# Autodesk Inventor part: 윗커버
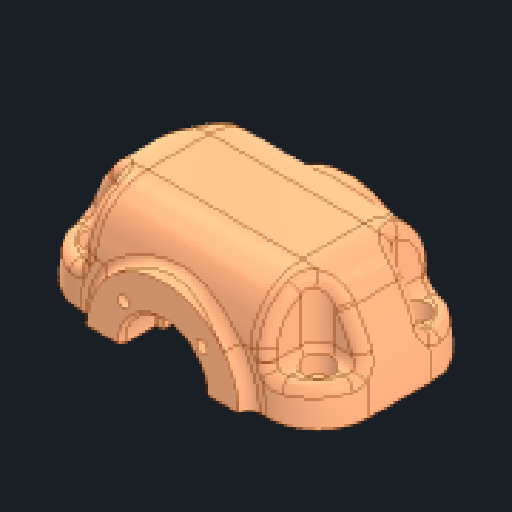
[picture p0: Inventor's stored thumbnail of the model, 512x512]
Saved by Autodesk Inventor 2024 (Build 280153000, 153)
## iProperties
Created: 2024-05
Part Number: 윗커버
Material: 알루미늄 6061
Document SubType Name: Modeling
Designer: kh_501
Density: 2.7 g/cm^3
Appearance: 기본값
Author: jhkim
Sending System: Autodesk Inventor 2025
Preprocessor: ST-DEVELOPER v20
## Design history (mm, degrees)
feature "솔리드1"
node "솔리드2"
